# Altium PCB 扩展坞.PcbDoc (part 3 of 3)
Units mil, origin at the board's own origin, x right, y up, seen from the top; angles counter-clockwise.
Board outline 3543.31 x 1968.5 mil, 4 copper layers (Top Layer 1, Layer1, Layer2, Bottom Layer 1), stack 62.337 mil thick; 191 components, 182 nets, 737 pads, 256 vias.
Unrouted connection lines stored in the file: 242.
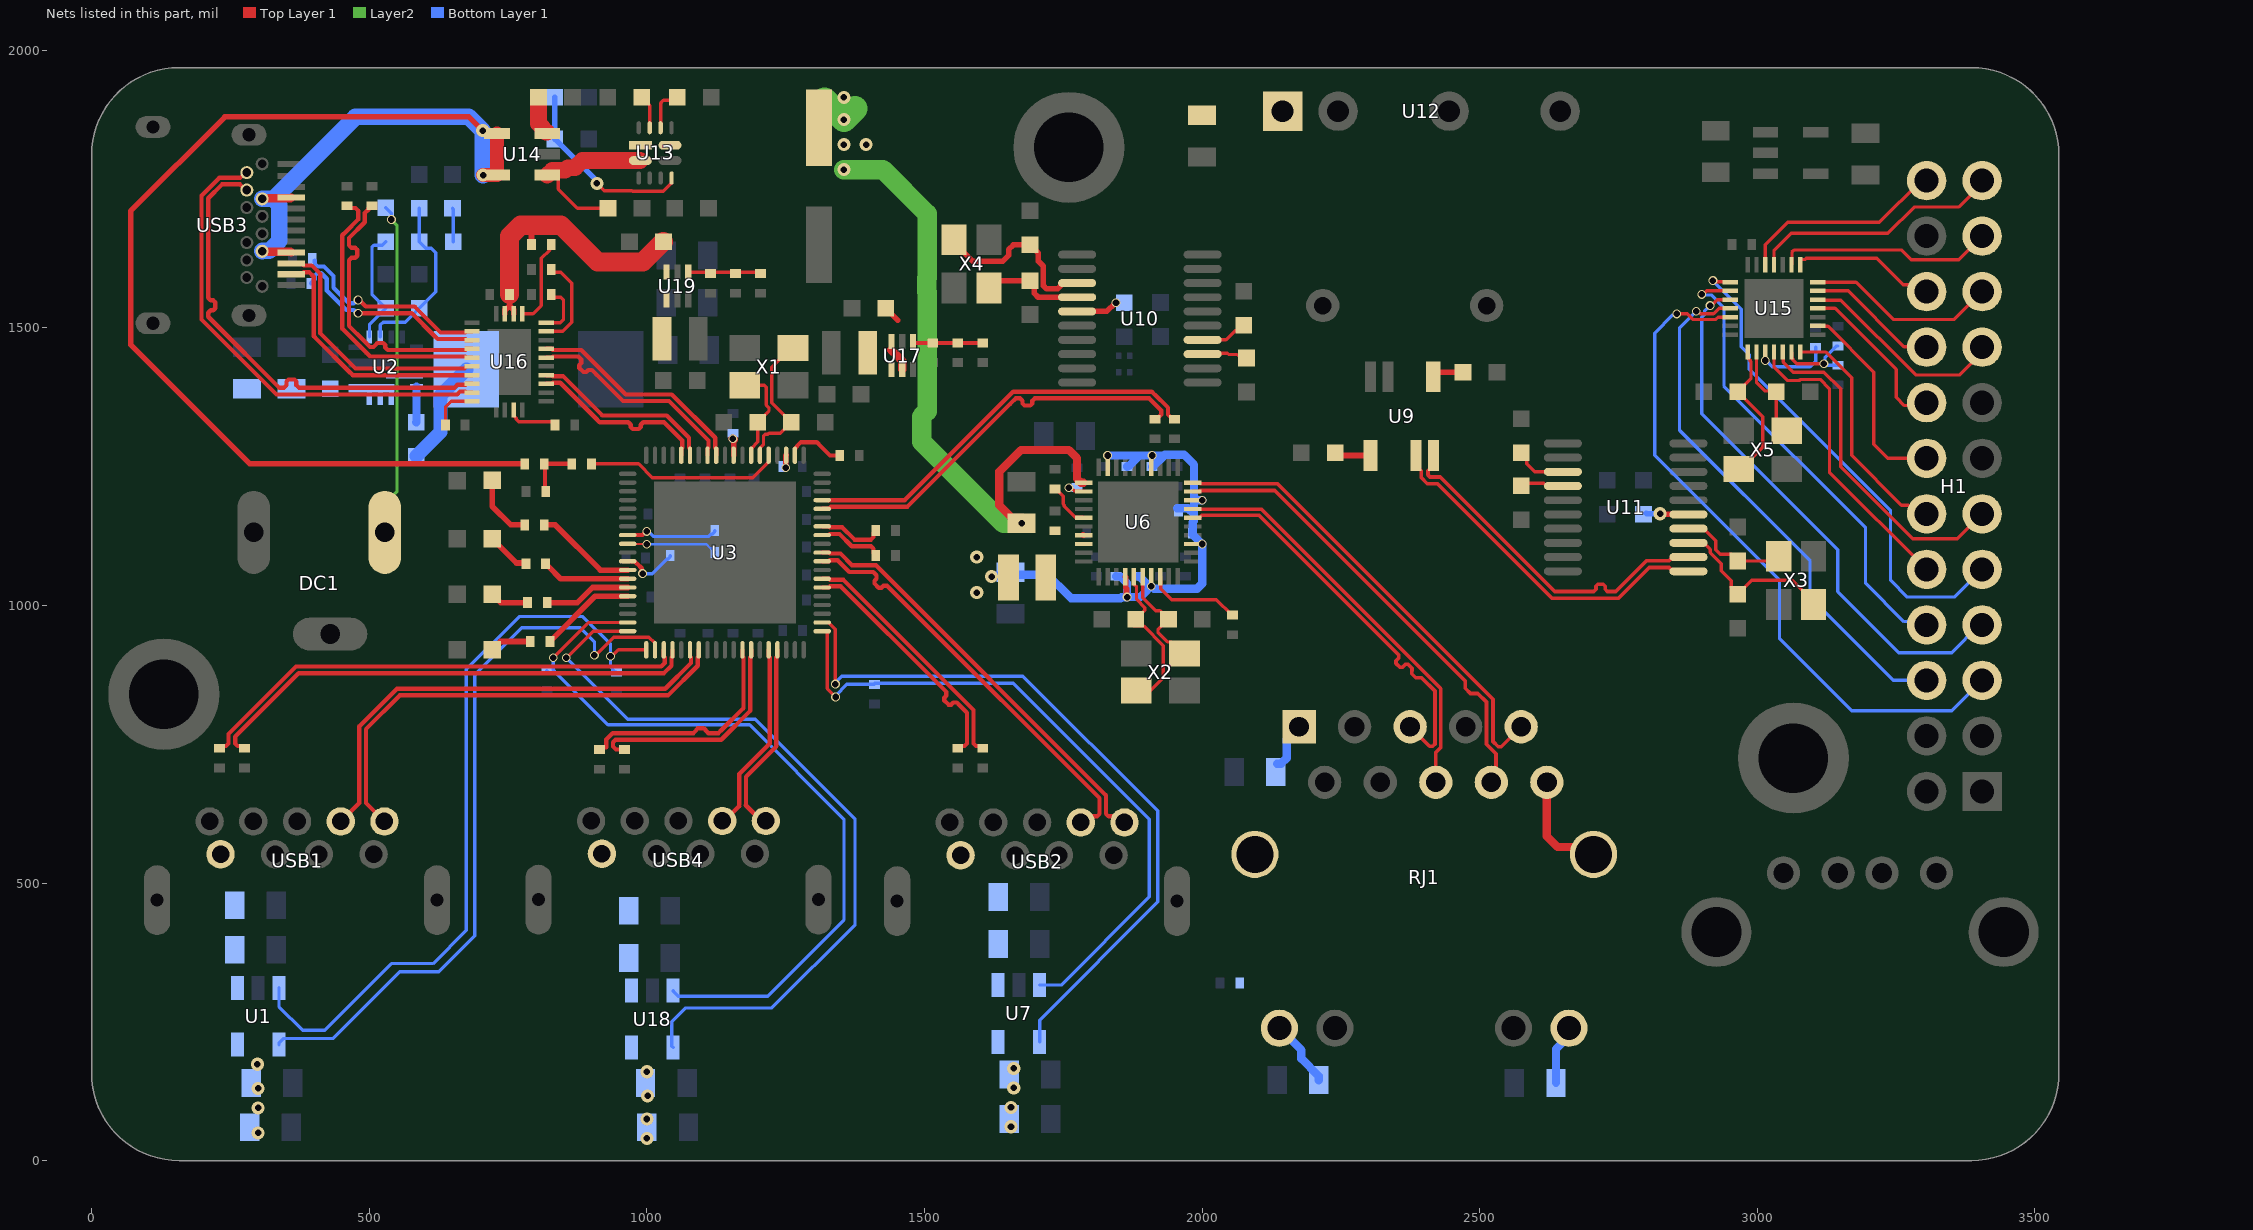
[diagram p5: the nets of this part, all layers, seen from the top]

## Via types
v1: diameter 15.75, hole 11.81, Top Layer 1 to Bottom Layer 1, tented both sides, 127 vias
v2: diameter 23.62, hole 11.81, Top Layer 1 to Bottom Layer 1, tented both sides, 118 vias
v3: diameter 15.75, hole 11.81, Top Layer 1 to Bottom Layer 1, 10 vias
v4: diameter 23.62, hole 11.81, Top Layer 1 to Bottom Layer 1, 1 vias

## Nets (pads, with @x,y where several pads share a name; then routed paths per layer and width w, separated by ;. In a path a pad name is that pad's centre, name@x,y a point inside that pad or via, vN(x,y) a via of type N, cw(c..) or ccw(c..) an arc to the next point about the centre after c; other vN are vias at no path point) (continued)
MDI2_N: RJ1.P6 U6.7 | length 753.1
  Top Layer 1 w6.7: U6.7@1983.4,1173.62 1983.99,1173.03 1996.97,1173.03 1997.03,1172.97 2107.16,1172.97 2110.95,1169.19 2430.02,850.11 2430.02,745.9 2430,744.04 2420.9,734.94 RJ1.P6@2420.9,681.45
MDI2_P: RJ1.P5 U6.6 | length 751.6
  Top Layer 1 w6.7: U6.6@1983.4,1157.87 1995.21,1157.87 1999.61,1162.27 2102.73,1162.27 2340,925 2354.18,910.82 2354.18,905.27 2349.23,900.33 2349.23,895.61 2356.32,888.52 2361.04,888.52 2366.4,893.88 2371.12,893.88 2378.21,886.79 2378.21,882.07 2377.79,881.65 2377.79,876.93 2384.88,869.85 2389.6,869.85 2395.15,869.85 2419.32,845.68 2419.32,834.32 2419.32,750.33 2415.4,746.41 2409.85,746.41 RJ1.P5@2374.8,781.45
MDI3_N: RJ1.P9 U6.10 | length 847.7
  Top Layer 1 w6.7: U6.10@1983.4,1220.87 1995.21,1220.87 1997.09,1218.99 2136.01,1218.99 2143.03,1211.97 2517.12,837.88 2524.15,830.85 2524.15,754.77 2533.36,745.56 2538.91,745.56 RJ1.P9@2574.8,781.45
MDI3_P: RJ1.P8 U6.9 | length 850
  Top Layer 1 w6.7: U6.9@1983.4,1205.12 1995.21,1205.12 1997.09,1206.99 2131.03,1206.99 2474.01,864.01 2474.01,850.99 2483.49,841.51 2496.51,841.51 2512.15,825.88 2512.15,749.8 2529.27,732.67 2529.27,689.83 RJ1.P8@2520.9,681.45
MISO: H1.20 U15.15 | length 275.5
  Top Layer 1 w6: U15.15@3077.24,1613.74 3077.24,1622.19 3078.18,1623.12 3086.3,1623.12 3088.18,1625 3215,1625 3262.59,1577.41 3292.59,1577.41 H1.20@3305,1565 ; H1.20@3310.64,1550.64 H1.20@3320,1560
MODE: R26.2 U10.13 | length 80.5
  Top Layer 1 w6: U10.13@2001.06,1452.63 2002.65,1454.22 2045.78,1454.22 2048,1452 2063,1452 R26.2@2075,1440
MOSI: H1.21 U15.16 | length 391.9
  Top Layer 1 w6: U15.16@3061.5,1613.74 3062.44,1614.68 3062.44,1636.49 3065.95,1640 3260,1640 3277.43,1622.57 3362.57,1622.57 H1.21@3405,1665
NetC17_1: C17.1 U2.7 | length 64.2
  Bottom Layer 1 w15: C17.1@585,1330 585.06,1330.06 585.06,1384.94 585.12,1385 U2.7@585.12,1394.18
NetC18_1: C18.1 R2.1 R3.2 U2.2 | length 314.5
  Bottom Layer 1 w6: U2.2@520.16,1483.55 520.16,1505.16 525,1510 565,1510 R3.2@590,1535 620,1565 620,1635 612,1643 602,1643 C18.1@590,1655 R2.1@590,1715
NetC18_2: C18.2 R1.2 | length 60.5
  Bottom Layer 1 w6: R1.2@650,1715 651.18,1713.82 C18.2@651.18,1655
NetC26_2: C26.2 U13.11 | length 60.8
  Top Layer 1 w6: C26.2@990.59,1915 1005.16,1900.43 U13.11@1005.16,1860.27
NetC43_1: C43.1 RJ1.P1 | length 87.3
  Bottom Layer 1 w15: C43.1@2135,715 2142.5,715 2152.5,725 2152.5,759.16 RJ1.P1@2174.8,781.45
NetC55_2: C55.2 U6.22 | length 29.1
  Top Layer 1 w6: v1(1760.21,1211.66) 1763.8,1211.66 1769.41,1206.06 1785.66,1206.06 U6.22@1786.6,1205.12
NetC60_1: C60.1 U9.6 | length 65.4
  Top Layer 1 w10: C60.1@2240,1275 2245,1270 U9.6@2303.31,1270
NetC61_2: C61.2 U9.3 | length 57.2
  Top Layer 1 w10: U9.3@2416.5,1411.73 2416.5,1412.2 2424.3,1420 C61.2@2470,1420
NetC62_1: C62.1 U11.5 | length 77
  Top Layer 1 w10: v2(2825,1165) 2825.59,1164.41 2875.47,1164.41 U11.5@2876.06,1163.82
  Bottom Layer 1 w10: C62.1@2800,1166.18 2801.18,1165 v2(2825,1165)
NetC63_2: C63.2 U10.5 | length 76.5
  Top Layer 1 w10: U10.5@1775,1529.4 1828.25,1529.4 1843.85,1545 v1(1845,1545)
NetC64_2: C64.2 U11.14 | length 81.2
  Top Layer 1 w6: C64.2@2575,1210 2585,1220 2615.62,1220 2620.62,1215 U11.14@2650,1215
NetC65_2: C65.2 U10.14 | length 89.5
  Top Layer 1 w6: U10.14@2001.06,1478.22 2043.22,1478.22 2059.51,1494.51 2070.7,1494.51 C65.2@2080,1503.82
NetC78_2: C78.2 R6.1 R7.2 U17.1 | length 126.8
  Top Layer 1 w7.74: U17.1@1479.69,1475.2 1479.69,1474.36 1481.33,1472.72 R6.1@1605,1472.72
NetC79_2: C79.2 R8.1 R9.2 U19.1 | length 131.3
  Top Layer 1 w6: U19.1@1074.69,1600.2 1202.52,1600.2 R8.1@1205,1597.72
NetC89_1: C89.1 R32.2 U15.6 | length 144
  Top Layer 1 w6: U15.6@3061.5,1456.26 3062.44,1455.32 3062.44,1445.48 3063.9,1444.02 3063.9,1441.98 3070.88,1435 v1(3120,1435)
  Bottom Layer 1 w6: C89.1@3145,1432.72 3122.28,1432.72 v1(3120,1435) 3121.87,1436.87 3121.87,1446.12 3143.03,1467.28 R32.2@3145,1467.29
NetLED1_2: LED1.2 R44.1 | length 119
  Top Layer 1 w10: LED1.2@721.47,1225.14 721.47,1178.53 755,1145 R44.1@780,1145
NetLED2_2: LED2.2 R45.1 | length 69.8
  Top Layer 1 w10: LED2.2@721.47,1020.14 736.61,1005 R45.1@785,1005
NetLED3_2: LED3.2 R46.1 | length 79.5
  Top Layer 1 w10: LED3.2@721.47,1120.14 765.27,1076.34 780.94,1076.34 R46.1@782.28,1075
NetLED4_2: LED4.2 R47.1 | length 74.7
  Top Layer 1 w10: LED4.2@721.47,920.14 736.34,935 R47.1@790,935
NetR4_1: R4.1 R5.2 U2.1 | length 213.2
  Bottom Layer 1 w6: U2.1@500.48,1483.55 500.48,1505.48 R5.2@530,1535 505,1560 505,1645 508.51,1648.51 523.51,1648.51 R4.1@530,1655
NetR10_1: R10.1 U16.23 | length 170.5
  Top Layer 1 w6: U16.23@819.06,1493.5 848.5,1493.5 865,1510 865,1580 845,1600 832.59,1600 827.72,1604.87 R10.1@827.72,1605
NetR11_1: R11.1 U16.24 | length 94.8
  Top Layer 1 w6: U16.24@819.06,1509.25 844.25,1509.25 850,1515 850,1550 845,1555 832.59,1555 827.72,1559.87 R11.1@827.72,1560
NetR12_1: R12.1 U16.25 | length 157.8
  Top Layer 1 w6: U16.25@775.75,1525 795,1525 810,1540 810,1625 825,1640 825,1647.28 R12.1@827.71,1650
NetR13_2: R13.2 U16.10 | length 84.4
  Top Layer 1 w6: R13.2@637.29,1325 637.29,1357.29 647.51,1367.51 U16.10@685.2,1367.51
NetR16_2: R16.2 U13.10 | length 78.9
  Top Layer 1 w6: U13.10@1024.84,1860.27 1024.84,1904.84 1030,1910 1050,1910 R16.2@1055,1915
NetR17_2: R17.2 U16.13 | length 93.2
  Top Layer 1 w6: U16.13@760.01,1351.76 760.01,1341.92 764.82,1337.1 764.82,1335.08 768.92,1330.98 829.7,1330.98 834.57,1326.11 R17.2@834.57,1325
NetR19_2: R19.2 U3.47 | length 30.2
  Top Layer 1 w10: U3.47@1156.4,1270.4 v1@1156.4,1298.4
  Top Layer 1 w15: v1(1155,1300) 1155,1299.8 v1@1156.4,1298.4
NetR20_1: R20.1 RJ1.11 | length 122.9
  Bottom Layer 1 w15: RJ1.11@2139.17,238.54 2178.74,198.97 2178.74,183.76 2210,152.5 R20.1@2210,145
NetR21_2: R21.2 U6.38 | length 171.5
  Top Layer 1 w6: U6.38@1924.37,1051.6 1925.31,1050.66 1925.31,1029.69 1945,1010 2025.75,1010 2053.03,982.71 R21.2@2055,982.71
NetR22_2: R22.2 U6.25 | length 82.3
  Top Layer 1 w6: R22.2@1735,1209.57 1736.97,1209.57 1750.05,1196.48 1750.05,1182.56 1751.84,1180.77 1751.84,1178.79 1771.83,1158.81 1785.66,1158.81 U6.25@1786.6,1157.87
NetR23_1: R23.1 U11.13 | length 95.1
  Top Layer 1 w6: R23.1@2575,1275 2585,1265 2585,1255 2599.41,1240.59 U11.13@2650,1240.59
NetR27_1: R27.1 U14.3 | length 70.4
  Top Layer 1 w30: R27.1@805,1915 805,1867.82 812.64,1860.18 812.64,1857.75 818,1852.4 U14.3@820.42,1852.4
NetR30_1: R30.1 RJ1.14 | length 108.2
  Bottom Layer 1 w15: R30.1@2637.4,140 2637.4,201.07 2660.83,224.49 RJ1.14@2660.83,238.54
NetR31_2: R31.2 U15.3 | length 126.2
  Bottom Layer 1 w6: v1@3012.55,1441.1 v1(3014.23,1441.1) 3015.9,1441.1 3027,1430 3095,1430 3105,1440 R31.2@3105,1465
NetR33_1: R33.1 RJ1.P10 RJ1.SHIELD0 RJ1.SHIELD1 | length 194.9
  Top Layer 1 w15: RJ1.P10@2620.9,681.45 2620.9,584.1 2640.05,564.95 2691.53,564.95 RJ1.SHIELD0@2704.92,551.55
NetR34_2: R34.2 U3.41 | length 22.7
  Top Layer 1 w10: v1(1250,1248.03) 1250.45,1248.48 1250.45,1269.95 U3.41@1250.9,1270.4
NetR37_2: R37.2 U3.68 | length 105.5
  Top Layer 1 w7.74: U3.68@965.5,1079.5 965.56,1079.44 U3.68@972.49,1079.44 ; v1(992.3,1057.24) 990.76,1058.77 990.76,1066.94 982.2,1075.51 981.34,1075.51 977.37,1079.47 U3.68@972.52,1079.47 ; U3.68@972.49,1079.44 U3.68@972.52,1079.47
  Bottom Layer 1 w6: v1(992.3,1057.24) 1009.53,1057.24 1035.44,1083.15 1037.41,1083.15 1042.29,1088.03 R37.2@1042.29,1090
NetR38_2: R38.2 U3.66 | length 164.5
  Top Layer 1 w4: U3.66@965.5,1110.9 965.95,1110.45 999.55,1110.45 v1(1000,1110)
  Bottom Layer 1 w4: v1(1000,1110) 1107.28,1110 1114.44,1102.84 1116.41,1102.84 1122.29,1096.97 R38.2@1122.29,1095
NetR39_2: R39.2 U3.65 | length 170
  Top Layer 1 w7.74: U3.65@965.5,1126.7 992.15,1126.73 998.71,1133.28 v1(999.79,1133.28) v1@1000.87,1133.28
  Bottom Layer 1 w6: v1(999.79,1133.28) 1002.43,1133.28 1011.55,1124.16 1111.45,1124.16 1115.44,1128.15 1117.41,1128.15 1122.29,1133.03 R39.2@1122.29,1135
NetR40_2: R40.2 U3.40 | length 107.8
  Top Layer 1 w7.74: U3.40@1266.7,1270.4 1266.7,1282.25 1270.59,1286.14 1270.59,1287.1 1277.51,1294.02 1305.98,1294.02 1309.99,1290.01 1330,1270 R40.2@1347.29,1270
NetR41_2: R41.2 R42.1 R43.1 | length 100.5
  Top Layer 1 w7.74: R43.1@817.72,1205 816.57,1206.14 816.57,1253.85 R41.2@815.43,1255 R42.1@865,1255
NetU4_1: U4.1 U17.4
NetU5_1: U5.1 U19.4
OC1: R18.2 U1.3 U3.1 | length 1378
  Top Layer 1 w6: v1(934.58,908.34) 937.22,908.34 948.88,920 U3.1@999,920
  Bottom Layer 1 w6: U1.3@337.4,311.18 337.4,277.6 380,235 420,235 540,355 615,355 675,415 675,885 770,980 885,980 934.58,930.42 v1(934.58,908.34) 934.58,890.42 938.16,886.84 938.16,884.87 943.03,880 R18.2@945,880
OC2: R36.2 U3.75 U18.3 | length 1387.5
  Top Layer 1 w6: v1(831.33,905.74) 850.46,924.87 894.79,969.2 U3.75@965.5,969.2
  Bottom Layer 1 w6: R36.2@820,882.71 824.87,877.84 837.16,877.84 ; v1(831.33,905.74) 831.33,883.67 837.16,877.84 ; U18.3@1047.4,306.18 1047.4,305 1056.21,296.18 1217.8,296.18 1355,433.38 1355,615 1185,785 930,785 837.16,877.84
OC3: R35.2 U3.20 U7.3 | length 1214
  Top Layer 1 w6: U3.20@1315.9,953.5 1323.85,953.5 1324.71,952.63 1324.71,850.29 v1(1340,835)
  Bottom Layer 1 w6: v1(1340,835) 1340,837.64 1360.08,857.71 R35.2@1410,857.71 ; R35.2@1410,860 1660,860 1905,615 1905,475 1746.18,316.18 U7.3@1707.4,316.18
P1C_SS_RX_N: U16.8 USB3.B10 | length 865.1
  Top Layer 1 w7.74: USB3.B10@279.59,1747.98 277.38,1747.98 267.11,1758.26 234.86,1758.26 210,1733.4 210,1565 210,1553.88 214.53,1549.35 219.14,1549.35 222.68,1545.8 222.68,1535.16 219.14,1531.61 214.53,1531.61 210,1527.08 210,1520 220,1510 335,1395 338,1392 346.58,1392 351.12,1396.53 351.12,1403.45 354.66,1407 365.31,1407 368.86,1403.45 368.86,1396.53 373.39,1392 395,1392 653.45,1392 658.58,1397.14 673.48,1397.14 675.36,1399.01 U16.8@685.2,1399.01
P1C_SS_RX_P: U16.9 USB3.B11 | length 867.8
  Top Layer 1 w7.74: USB3.B11@279.58,1779.48 276.6,1779.48 267.11,1770 230,1770 198.26,1738.26 198,1738 198,1515.03 333.03,1380 658.42,1380 663.55,1385.14 673.48,1385.14 675.36,1383.26 U16.9@685.2,1383.26
P1C_SS_TX_N: C31.2 U16.5 | length 503.2
  Top Layer 1 w7.74: C31.2@460,1719.57 464,1715.57 475.47,1715.57 480,1711.03 480,1695 458.54,1673.54 451.51,1666.51 451.51,1600 451.51,1498.49 458.54,1491.46 494.85,1455.15 501.88,1448.12 673.48,1448.12 675.36,1446.25 U16.5@685.2,1446.25
P1C_SS_TX_P: C30.2 U16.4 | length 503.5
  Top Layer 1 w7.74: C30.2@505,1719.57 503.03,1719.57 499.02,1715.57 499.02,1713.6 492,1706.57 492,1690.03 463.51,1661.54 463.51,1655 463.51,1648.42 468.05,1643.88 474.97,1643.88 478.51,1640.34 478.51,1629.69 474.97,1626.14 468.05,1626.14 463.51,1621.61 463.51,1600 463.51,1503.46 490,1476.97 501.41,1465.57 507.82,1465.57 514.66,1472.41 525.31,1472.41 528.86,1468.86 528.86,1464.66 533.39,1460.12 555,1460.12 673.48,1460.12 675.36,1462 U16.4@685.2,1462
PE1: U1.4 U3.2 | length 1329.6
  Top Layer 1 w6: v1(905.61,910.43) 908.24,910.43 940.56,942.75 948.97,942.75 949.16,942.56 981.84,942.56 982.03,942.75 1003.76,942.75 1014.09,932.42 1014.09,920.61 U3.2@1014.7,920
  Bottom Layer 1 w6: U1.4@337.4,208.82 337.4,211.19 346.21,220 435,220 555,340 625,340 690,405 690,875 775,960 880,960 905.61,934.39 v1(905.61,910.43)
PE2: U3.76 U18.4 | length 1410.4
  Top Layer 1 w6: v1(855,905.74) 855.74,905.74 903.5,953.5 U3.76@965.5,953.5
  Bottom Layer 1 w6: v1(855,905.74) 965.74,795 1195,795 1375,615 1375,425 1225,275 1070,275 1045,250 1045,206.22 U18.4@1047.4,203.82
PE3: U3.21 U7.4 | length 1320.3
  Top Layer 1 w6: U3.21@1315.9,969.2 1327.71,969.2 1339.59,957.33 v1(1339.59,858.26)
  Bottom Layer 1 w6: v1(1339.59,858.26) 1339.59,860.9 1351.28,872.59 1677.41,872.59 1920,630 1920,465.86 1707.4,253.26 U7.4@1707.4,213.82
PR1: R48.1 R49.2 U13.6 | length 341.2
  Top Layer 1 w6: v2(910,1760) 923,1747 973.32,1747 974.13,1746.19 1029.38,1746.19 1044.53,1761.34 U13.6@1044.53,1769.73
  Bottom Layer 1 w10: R49.2@834.41,1915 R48.1@834.41,1840 907.39,1767.02 907.39,1762.61 v2(910,1760)
RTS0: H1.23 U15.18 | length 455.4
  Top Layer 1 w6: U15.18@3030,1613.74 3030,1638.95 3061.05,1670 3235,1670 3282.5,1717.5 3362.5,1717.5 3405,1760 H1.23@3405,1765
RX0_N: U3.53 U16.17 | length 331
  Top Layer 1 w7.74: U16.17@819.06,1399.01 828.9,1399.01 830.78,1400.89 844.12,1400.89 907.97,1337.03 915,1330 945,1330 966.61,1330 971.14,1325.47 971.14,1321.3 974.69,1317.76 985.34,1317.76 988.88,1321.3 988.88,1325.47 993.42,1330 1010,1330 1030.91,1330 1063.85,1297.06 1063.85,1284.1 1062,1282.25 U3.53@1062,1270.4
RX0_P: U3.52 U16.18 | length 335.9
  Top Layer 1 w7.74: U16.18@819.06,1414.76 828.9,1414.76 830.78,1412.89 849.09,1412.89 919.97,1342 1035.88,1342 1075.85,1302.03 1075.85,1284.1 1077.7,1282.25 U3.52@1077.7,1270.4
RX1_N: U3.6 USB1.6 | length 854.3
  Top Layer 1 w7.74: USB1.6@448.74,610.87 482.11,644.23 482.11,782.08 550.03,850 1033.22,850 1079.6,896.38 1079.6,906.25 1077.7,908.15 U3.6@1077.7,920
RX1_P: U3.7 USB1.5 | length 854.3
  Top Layer 1 w7.74: USB1.5@527.48,610.87 494.11,644.24 494.11,777.11 555,838 1038.19,838 1091.6,891.41 1091.6,906.25 1093.5,908.15 U3.7@1093.5,920
RX2_N: U3.15 USB4.6 | length 347.6
  Top Layer 1 w7.74: USB4.6@1133.75,605.87 1166.26,638.39 ; 1166.52,641.9 1166.52,696.52 1221.3,751.3 1221.3,906.25 1219.4,908.15 U3.15@1219.4,920
RX2_P: U3.16 USB4.5 | length 351.9
  Top Layer 1 w7.74: USB4.5@1212.47,605.87 1178.26,640.09 1178.52,640.34 1178.52,691.55 1233.3,746.33 1233.3,906.25 1235.2,908.15 U3.16@1235.2,920
RX3_N: U3.28 USB2.6 | length 761.4
  Top Layer 1 w7.74: U3.28@1315.9,1079.5 1327.75,1079.5 1329.6,1081.35 1343.65,1081.35 1364.71,1060.29 1395.29,1060.29 1407.74,1060.29 1413.59,1054.44 1413.59,1048.03 1409.98,1044.42 1409.98,1039.4 1417.51,1031.87 1422.52,1031.87 1426.13,1035.48 1432.55,1035.48 1464.01,1004.01 1815.14,652.89 1815.14,624.55 1810.61,620.02 1790.06,620.02 USB2.6@1781.77,611.73
RX3_P: U3.29 USB2.5 | length 764.4
  Top Layer 1 w7.74: U3.29@1315.9,1095.2 1327.75,1095.2 1329.6,1093.35 1348.62,1093.35 1369.68,1072.29 1412.71,1072.29 1827.14,657.86 1827.14,624.55 1831.68,620.02 1852.23,620.02 USB2.5@1860.51,611.73
RX4_N: C39.1 U3.35 | length 742.5
  Top Layer 1 w7.74: U3.35@1315.9,1189.7 1327.75,1189.7 1327.81,1189.63 1464.63,1189.63 1659.74,1384.74 1909.54,1384.74 1914.28,1380 1914.65,1380 1938.5,1356.14 1938.5,1343.97 1943.04,1339.43 1946,1339.43 C39.1@1950,1335.43
RX4_P: C40.1 U3.34 | length 740.8
  Top Layer 1 w7.74: U3.34@1315.9,1173.9 1327.75,1173.9 1331.74,1177.89 1469.5,1177.89 1655,1363.4 1664.6,1373 1672.08,1373 1676.61,1368.47 1676.61,1363.58 1680.16,1360.03 1690.8,1360.03 1694.35,1363.58 1694.35,1368.47 1698.88,1373 1720,1373 1890,1373 1904.68,1373 1926.5,1351.17 1926.5,1343.97 1921.97,1339.43 1919.01,1339.43 C40.1@1915,1335.43
RXD0: H1.9 U15.22 | length 903.1
  Top Layer 1 w6: v1(2920,1585) 2921.82,1583.18 2950.32,1583.18 U15.22@2951.26,1582.24
  Bottom Layer 1 w6: v1(2920,1585) 2971.19,1533.81 2971.19,1465.41 2985.39,1451.22 2985.39,1425.39 3240,1170.78 3240,1045 3270,1015 3355,1015 H1.9@3405,1065
RXD1: H1.11 U15.5 | length 609.1
  Top Layer 1 w6: U15.5@3045.75,1456.26 3046.69,1455.32 3046.69,1438.31 3065,1420 3120,1420 3150,1390 3150,1250 3280,1120 3360,1120 H1.11@3405,1165
S_XI: R24.1 U11.4 X3.3 | length 199.6
  Top Layer 1 w6: U11.4@2876.06,1138.22 2903.19,1138.22 2925,1116.41 2925,1100 2933,1092 2953,1092 R24.1@2965,1080 3030.2,1080 X3.3@3038.51,1088.3
S_XO: C66.1 U11.3 X3.1 | length 313
  Top Layer 1 w6: U11.3@2876.06,1112.63 2903.19,1112.63 2915,1100.82 2915,1095.26 2935,1075.26 2935,1062.5 2953,1044.5 2953,1032 C66.1@2965,1020 2990,1045 3063.11,1045 3101.49,1006.62 X3.1@3101.49,1001.7
SCK: H1.19 U15.14 | length 344.8
  Top Layer 1 w6: U15.14@3108.74,1582.24 3177.76,1582.24 3245,1515 3355,1515 H1.19@3405,1565
SCL: H1.16 U15.11 | length 300.1
  Top Layer 1 w6: U15.11@3108.71,1535 3140,1535 3250,1425 3250,1375 3265,1360 3300,1360 H1.16@3305,1365
SCS0: H1.18 U15.13 | length 256.4
  Top Layer 1 w6: U15.13@3108.74,1566.5 3163.5,1566.5 3264.08,1465.92 3304.08,1465.92 H1.18@3305,1465 ; H1.18@3305,1467.46 3312.54,1467.46 H1.18@3320,1460
SCS1: H1.12 U15.7 | length 430.4
  Top Layer 1 w6: U15.7@3077.24,1456.26 3123.74,1456.26 3170,1410 3170,1270 3259.58,1180.42 3272.03,1180.42 3277.45,1175 3295,1175 H1.12@3305,1165
SDA: H1.17 U15.12 | length 379.1
  Top Layer 1 w6: U15.12@3108.74,1550.74 3109.68,1549.8 3150.2,1549.8 3285,1415 3365,1415 3405,1455 H1.17@3405,1465
SS1_RX_N: U16.7 USB3.A11 | length 467
  Top Layer 1 w7.74: USB3.A11@359.32,1596.41 378.51,1596.41 382.35,1600.26 391.79,1600.26 400,1592.05 400,1485 407.03,1477.97 463.22,1421.78 470.25,1414.75 U16.7@685.2,1414.75
SS1_RX_P: U16.6 USB3.A10 | length 468.6
  Top Layer 1 w7.74: USB3.A10@359.32,1616.11 378.51,1616.11 382.35,1612.26 396.76,1612.26 412,1597.02 412,1489.97 475.22,1426.75 671.61,1426.75 675.36,1430.5 U16.6@685.2,1430.5
SS1_TX_N: C73.1 U16.3 | length 358.9
  Top Layer 1 w7.74: v1(480,1526.25) 493.91,1526.25 576.78,1526.25 616.38,1486.65 623.41,1479.62 673.49,1479.62 675.36,1477.75 U16.3@685.2,1477.75
  Bottom Layer 1 w7.74: C73.1@395,1580 C73.1@399,1584 ; 402.52,1587.52 402.52,1593.89 407.05,1598.42 413.46,1598.42 423.59,1588.3 423.59,1567.18 458.64,1532.13 471.96,1532.13 477.83,1526.25 v1(480,1526.25)
SS1_TX_P: C72.1 U16.2 | length 358.2
  Top Layer 1 w7.74: v1(480,1550) 482.17,1550 493.91,1538.25 581.75,1538.25 628.38,1491.62 673.49,1491.62 675.36,1493.49 U16.2@685.2,1493.49
  Bottom Layer 1 w7.74: C72.1@401.72,1621 401.72,1615.75 407.05,1610.42 418.44,1610.42 435.59,1593.27 435.59,1572.15 463.61,1544.13 471.96,1544.13 477.83,1550 v1(480,1550)
SW: C17.2 L2.1 U2.6 | length 193.5
  Bottom Layer 1 w25: C17.2@585,1268.82 628.45,1312.26 628.45,1378.44 L2.1@675,1425
SW2: L3.1 U6.28
SWDIO/TMS: H1.5 U15.26 | length 1241.5
  Top Layer 1 w6: v1(2855,1525) 2873.97,1525 2883.97,1515 2925.18,1515 2929.44,1519.26 U15.26@2951.26,1519.26
  Bottom Layer 1 w6: v1(2855,1525) 2853.13,1523.13 2848.13,1523.13 2815,1490 2815,1270 3040,1045 3040,940 3170,810 3350,810 H1.5@3405,865
SYS+5V: C37.1 C44.2 C45.2 C57.2 C76.2 C77.2 C82.2 C83.2 C93.2 C94.2 C97.2 C98.2 C101.2 R12.2 U1.5 U6.21 U6.27 U7.5 U12.1 U13.1 U13.8 U16.26 U16.27 U17.3 U17.5 U18.5 U19.3 | length 1861.4
  Top Layer 1 w10: U16.27@744.25,1525 744.25,1532.72 745.31,1533.78 746.86,1533.78 752.71,1539.64 ; C77.2@752.71,1560 752.71,1539.64 ; U16.26@760,1525 760,1532.72 758.94,1533.78 758.57,1533.78 752.71,1539.64 ; R12.2@792.28,1650 792.28,1682.28 795,1685 ; C57.2@1430.59,1535 1452.24,1513.35 ; U6.27@1785.54,1127.44 U6.27@1786.6,1126.38
  Top Layer 1 w15: 1440,1460 1450.31,1449.69 1450.59,1449.69 1460.01,1440.27 U17.5@1460.01,1424.8 ; v2(1675,1147.6) 1667.5,1147.6 1635,1180.1 1635,1241.17 1673.83,1280 1760,1280 1774.79,1265.21 1774.79,1228 1781.91,1220.87 U6.21@1786.6,1220.87
  Top Layer 1 w35: C77.2@752.71,1560 752.71,1664.5 773.22,1685 795,1685 845,1685 911.5,1618.5 992.72,1618.5 1029.22,1655 C76.2@1030,1655
  Layer2 w35: v2(1355,1785) 1425,1785 1505,1705 1505,1589.64 1504.41,1589.05 1504.41,1564.71 1505,1564.12 1505,1350 1495,1340 1495,1295 1642.4,1147.6 v2(1675,1147.6)
  Layer2 w45: 1320,1910 v2(1355,1875) 1375,1895 ; U12.1@2140,1895 U12.1@2150,1885
  other v2: 1000,40 300,50 1655.84,61.03 1000,75 300,95 1655.84,96.03 1001.48,116.48 300,130 1660.84,131.03 1000,160 1660.84,166.03 298.52,173.52 1355,1830 1395,1830 1355,1915
TCK: H1.8 U15.23 | length 846.6
  Top Layer 1 w6: v1(2900,1560) 2902.64,1560 2909.14,1566.5 U15.23@2951.26,1566.5
  Bottom Layer 1 w6: v1(2900,1560) 2900.84,1559.16 2916.87,1559.16 2940,1536.03 2940,1395 3195,1140 3195,1040 3264.08,970.92 3299.08,970.92 H1.8@3305,965
TDI: H1.6 U15.25 | length 964.3
  Top Layer 1 w6: v1(2890,1530) 2892.64,1530 2897.51,1525.13 2921.16,1525.13 2931.03,1535 U15.25@2951.27,1535
  Bottom Layer 1 w6: v1(2890,1530) 2860,1500 2860,1315 3095,1080 3095,1015 3245,865 H1.6@3305,865
TDO: H1.7 U15.24 | length 989.7
  Top Layer 1 w6: v1(2915,1540) 2917.38,1540 2928.12,1550.74 U15.24@2951.26,1550.74
  Bottom Layer 1 w6: v1(2915,1540) 2904.87,1529.87 2904.87,1523.84 2900,1518.97 2900,1345 3145,1100 3145,1025 3255,915 3350,915 3400,965 H1.7@3405,965
TRST: H1.14 U15.9 | length 371.2
  Top Layer 1 w6: U15.9@3108.74,1503.5 3109.68,1502.56 3127.44,1502.56 3210,1420 3210,1290 3235,1265 H1.14@3305,1265
TX0_N: U3.50 U16.20 | length 400.1
  Top Layer 1 w7.74: U16.20@819.06,1446.26 828.9,1446.26 830.78,1448.14 863.14,1448.14 876.86,1448.14 877.54,1447.46 882.07,1442.92 882.07,1436.51 878.3,1432.73 878.3,1427.72 885.82,1420.19 890.84,1420.19 894.62,1423.97 901.03,1423.97 910,1415 957,1368 1040.03,1368 1111.1,1296.93 1111.1,1284.15 1109.2,1282.25 U3.50@1109.2,1270.4
TX0_P: U3.49 U16.21 | length 402.6
  Top Layer 1 w7.74: U16.21@819.06,1462.01 828.9,1462.01 830.78,1460.14 881.84,1460.14 961.97,1380 1045,1380 1123.1,1301.9 1123.1,1284.15 1125,1282.25 U3.49@1125,1270.4
TX1_N: C33.2 U3.3 | length 900.5
  Top Layer 1 w7.74: C33.2@230,742.71 234.01,746.72 241.97,746.72 246.5,751.25 246.5,768.47 368.03,890 1025.97,890 1032.35,896.38 1032.35,906.3 1030.5,908.15 U3.3@1030.5,920
TX1_P: C32.2 U3.4 | length 900.5
  Top Layer 1 w7.74: C32.2@275,742.71 271,746.72 263.04,746.72 258.5,751.25 258.5,763.5 373,878 544.97,878 1030.94,878 1044.35,891.41 1044.35,906.3 1046.2,908.15 U3.4@1046.2,920
TX2_N: C28.2 U3.12 | length 412.3
  Top Layer 1 w7.74: C28.2@915,740.43 919.01,744.43 926.97,744.43 926.97,758.44 938.53,770 1080,770 1083.87,770 1088.4,774.53 1088.4,775.39 1091.95,778.93 1102.6,778.93 1106.14,775.39 1106.14,774.53 1110.68,770 1129.05,770 1135,775.95 1174.05,815 1174.05,906.3 1172.2,908.15 U3.12@1172.2,920
TX2_P: C27.2 U3.13 | length 412
  Top Layer 1 w7.74: C27.2@960,740.43 944.57,740.43 938.97,746.03 938.97,753.47 943.5,758 1134.02,758 1186.05,810.03 1186.05,906.3 1187.9,908.15 U3.13@1187.9,920
TX3_N: C35.2 U3.25 | length 448.6
  Top Layer 1 w7.74: U3.25@1315.9,1032.2 1327.75,1032.2 1329.78,1034.23 1349.17,1034.23 1524.2,859.2 1539.48,843.92 1539.48,837.51 1535.78,833.81 1535.78,828.79 1543.31,821.27 1548.33,821.27 1552.02,824.96 1558.44,824.96 1561.7,821.7 1576.63,806.76 1576.63,751.25 1572.1,746.72 1564.01,746.72 C35.2@1560,742.71
TX3_P: C34.2 U3.26 | length 450.9
  Top Layer 1 w7.74: U3.26@1315.9,1048 1327.75,1048 1329.78,1045.97 1354.03,1045.97 1588.37,811.63 1588.37,751.25 1592.91,746.72 1601,746.72 C34.2@1605,742.71
TX4_N: C36.1 U3.32 | length 117.8
  Top Layer 1 w7.74: U3.32@1315.9,1142.4 1327.75,1142.4 1329.6,1140.55 1352.04,1140.55 1374.09,1118.5 1403.75,1118.5 1408.28,1123.03 1408.28,1131 C36.1@1412.28,1135
TX4_P: C29.1 U3.31 | length 117.8
  Top Layer 1 w7.74: U3.31@1315.9,1126.7 1327.75,1126.7 1329.6,1128.55 1347.07,1128.55 1369.12,1106.5 1403.75,1106.5 1408.28,1101.97 1408.28,1094 C29.1@1412.28,1090
TXD0: H1.24 U15.19 | length 374.2
  Top Layer 1 w6: U15.19@3014.26,1613.74 3014.26,1649.26 3055,1690 3220,1690 3295,1765 H1.24@3305,1765
TXD1: H1.10 U15.4 | length 542.3
  Top Layer 1 w6: U15.4@3029.96,1456.26 3029.96,1430.04 3055,1405 3075.69,1405 3077.69,1407 3113.49,1407 3130,1390.49 3130,1240 H1.10@3305,1065
USBLED1: R44.2 U3.69 | length 183.7
  Top Layer 1 w10: R44.2@815.43,1145 835,1145 916.3,1063.7 U3.69@965.5,1063.7
USBLED2: R46.2 U3.70 | length 160.1
  Top Layer 1 w10: R46.2@817.71,1075 817.71,1073.03 820.59,1070.15 822.56,1070.15 844.71,1048 U3.70@965.5,1048
USBLED3: R45.2 U3.71 | length 158.6
  Top Layer 1 w10: R45.2@818.15,1005 R45.2@820.43,1005 875,1005 902.2,1032.2 U3.71@965.5,1032.2
USBLED4: R47.2 U3.72 | length 175
  Top Layer 1 w10: R47.2@825.43,935 825.43,936.97 828.3,939.84 830.27,939.84 906.93,1016.5 U3.72@965.5,1016.5
VBUS: R41.1 U14.4 U14.5 USB3.A4 USB3.A9 USB3.B4 USB3.B9 | length 2624.8
  Top Layer 1 w10: v2(704.4,1855) 679.4,1880 240,1880 70.19,1710.19 70.19,1469.81 285,1255 R41.1@780,1255
  Top Layer 1 w15: USB3.B4@307.14,1637.76 308.13,1636.77 358.33,1636.77 USB3.A9@359.32,1635.78 ; USB3.B9@307.15,1732.24 308.14,1733.23 358.33,1733.23 USB3.A4@359.32,1734.22
  Top Layer 1 w25: v2(705,1775) U14.5@730,1775 ; U14.5@730,1777.85 U14.4@730,1849.8
  Bottom Layer 1 w30: USB3.B4@307.14,1637.76 307.82,1638.43 319.91,1638.43 337.96,1656.48 337.96,1721.52 327.24,1732.24 ; USB3.B9@307.15,1732.24 327.24,1732.24 ; v2(705,1775) 704.4,1775.6 v2(704.4,1855) 679.4,1880 475,1880 327.24,1732.24
VBUS2: C84.2 C85.2 U1.1 USB1.1
VBUS3: C95.2 C96.2 U7.1 USB2.1
VBUS4: C99.2 C100.2 U18.1 USB4.1
VBUS_C: R14.2 U13.2 U14.1 | length 313.2
  Top Layer 1 w6: U14.1@833.55,1777.6 840.2,1770.95 840.2,1749.8 875,1715 R14.2@930,1715
  Top Layer 1 w30: U14.1@820.9,1775 829.65,1783.75 852.99,1783.75 857.74,1788.5 870.98,1788.5 883.7,1801.23 U13.2@988.43,1801.23
VBUSET0: R42.2 U3.43 | length 352.9
  Top Layer 1 w6: R42.2@900.43,1255 985,1255 1009.85,1230.15 1190.96,1230.15 1219.4,1258.59 U3.43@1219.4,1270.4
VDD1V0: C50.2 C51.2 C52.2 C53.2 C54.2 C68.2 C69.2 C70.2 L3.2 U6.3 U6.8 U6.14 U6.19 U6.34 U6.37 | length 1007.8
  Top Layer 1 w10: U6.34@1861.38,1051.6 1862.44,1050.54 1862.44,1031.37 1863.9,1029.91 1863.9,1016.1 v1(1865,1015)
  Bottom Layer 1 w15: v4(1620.81,1051.86) 1622.46,1053.5 1653.5,1053.5 1655,1055 C54.2@1715,1055 ; C54.2@1717.34,1059.63 1763.8,1013.16 1853.24,1013.16 1854.94,1014.86 1864.86,1014.86 v1(1865,1015) ; v1(1829.89,1270) 1886.97,1270 ; C69.2@1845,1052.29 1845.38,1051.91 1853.24,1051.91 1864.86,1040.3 1864.86,1015.14 v1(1865,1015) ; C51.2@1865,1250 1865.37,1250.37 1867.34,1250.37 1886.97,1270 ; C70.2@1885,1052.29 1886.97,1052.29 1904.62,1034.63 1908.49,1034.63 v1(1908.64,1034.49) ; 1901.78,1027.84 1889.09,1015.14 1865.14,1015.14 v1(1865,1015) ; C52.2@1910,1250 1911.97,1250 1931.34,1269.37 ; v1@1913.33,1030 1991.21,1030 2000.35,1039.14 v1(2000.35,1110.63) ; C68.2@1955,1175 1975,1175 1985.43,1164.57 ; C50.2@1982.71,1128.03 v1@1999.97,1110.77 ; C50.2@1983.09,1127.66 1983.09,1149.8 1985.43,1152.14 1985.43,1164.57 ; 1985.43,1189.37 1985.43,1164.57 ; v1(2000.35,1189.37) 2000.21,1189.51 1990.92,1189.51 1985.43,1195 1985.43,1253.55 1967.36,1271.62 1932.96,1271.62 1931.34,1270 v1(1910,1270) 1886.97,1270
  other v2: 1594.19,1023.14 1594.19,1086.86
VIN: C19.1 C20.1 C21.1 DC1.1 R4.2 U2.8 | length 602
  Layer2 w6: DC1.1@528.15,1131.55 528.15,1182.61 550,1204.46 550,1685 v1(540,1695)
  Bottom Layer 1 w6: R4.2@530,1716.18 540,1706.18 v1(540,1695)
X_N: U9.5 U11.1 | length 640.9
  Top Layer 1 w6.7: U9.5@2385,1270 2385,1252.28 2394.75,1242.53 2394.75,1230.12 2405.7,1219.17 2423.86,1219.17 2630.03,1013 2749.97,1013 2805.22,1068.24 2841.19,1068.24 2847.99,1061.45 U11.1@2876.06,1061.45
X_P: U9.4 U11.2 | length 638.4
  Top Layer 1 w6.7: U9.4@2416.5,1270 2416.5,1252.28 2406.75,1242.53 2406.75,1235.09 2410.67,1231.17 2428.83,1231.17 2635,1025 2690,1025 2705.4,1025 2709.32,1028.92 2709.32,1034.61 2712.66,1037.95 2722.68,1037.95 2726.02,1034.61 2726.02,1028.92 2729.95,1025 2745,1025 2750,1030 2800.25,1080.24 2841.19,1080.24 2847.99,1087.04 U11.2@2876.06,1087.04
XI: C23.2 U3.45 X1.3 | length 177.8
  Top Layer 1 w6: X1.3@1176.7,1396.6 1211.49,1396.6 1215,1393.09 1215,1360.86 1220,1355.86 1220,1350 C23.2@1200,1330 1200,1294.31 1187.9,1282.21 U3.45@1187.9,1270.4
XI0: R25.1 U10.4 X4.3 | length 185.2
  Top Layer 1 w10: X4.3@1616.49,1571.7 1629.8,1585 R25.1@1690,1585 1698.11,1576.89 1698.11,1561.89 1705,1555 U10.4@1775,1555
XI2: C88.1 U15.1 X5.3 | length 261.9
  Top Layer 1 w6: X5.3@2966.69,1245.55 2970.63,1245.55 3010,1284.92 3010,1340 C88.1@2965,1385 2988.5,1408.5 2988.5,1438.64 2987.56,1439.58 2987.56,1441.97 2984.05,1445.48 2983.7,1445.48 2982.76,1446.42 U15.1@2982.76,1456.26
XO: C22.1 U3.44 X1.1 | length 263.4
  Top Layer 1 w6: U3.44@1203.7,1270.4 1203.7,1282.72 1210,1289.02 1210,1304.49 1213.51,1308 1217.9,1308 1219.9,1310 1240,1310 C22.1@1260,1330 1225,1365 1225,1429.15 1259.35,1463.5 X1.1@1263.3,1463.5
XO0: C67.1 U10.3 X4.1 | length 325.7
  Top Layer 1 w10: X4.1@1553.51,1658.31 1553.51,1653.38 1586.89,1620 1641.11,1620 1651.43,1630.32 1651.43,1640.84 1660,1649.41 C67.1@1690,1649.41 1705,1634.41 1705,1620 1714,1611 1714,1575.86 1719.86,1570 1739.85,1570 1745.71,1575.86 1745.71,1577.25 1749.05,1580.59 U10.3@1775,1580.59
XO2: C87.2 U15.2 X5.1 | length 175.9
  Top Layer 1 w6: U15.2@2998.5,1456.26 2998.5,1401.5 3013.92,1386.08 3033.33,1386.08 C87.2@3034.41,1385 3034.41,1333.35 X5.1@3053.31,1314.45
XTAL1: C42.1 U6.35 X2.1 | length 315.8
  Top Layer 1 w6: X2.1@1871.69,846.53 1906.53,846.53 1930,870 1930,927.63 1894.63,963 1877,963 1875.59,964.41 1875.59,985 C42.1@1884.08,985 ; U6.35@1877.13,1051.6 1878.07,1050.66 1878.07,1037.52 1881.93,1033.66 1881.93,1010.85 1896.7,996.08 1896.7,991.11 C42.1@1880.59,975
XTAL2: C41.2 U6.36 X2.3 | length 190.2
  Top Layer 1 w6: U6.36@1892.87,1051.6 1892.87,1014.05 1916.84,990.08 1924.33,990.08 1929.41,985 C41.2@1945,985 ; C41.2@1939.41,975 1920.58,956.17 1920.58,951.2 1937.69,934.09 1943.75,934.09 1958.31,919.53 X2.3@1958.31,913.47
pads on no net: *1.1 *2.1 *.1 U2.4 U2.5 U3.39 U3.42 U3.57 U3.58 U3.59 U3.60 U3.61 U3.63 U3.64 U6.24 U6.31 U8.4 U10.10 U10.11 U10.12 U10.17 U10.18 U10.19 U10.20 U11.10 U11.11 U11.12 U11.17 U11.18 U11.19 U11.20 U16.11 U16.12 U16.14 U16.15 U16.16 U16.22 U19.6 USB3.A8 USB3.B8

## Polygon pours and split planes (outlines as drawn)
GND on Bottom Layer 1 "GND_L04_P037" (solid, pour order 37): 1088.3,1633.3 1088.3,1659 1109,1659 1130,1680 1130,1815 1150,1835 1300,1835 1340,1795 1340,1500 1320,1480 1260,1480 1250,1470 1250,1420 1285,1385 1415,1385 1415,1380.7 1425,1370.7 1425,1340 1420,1340 1390,1310 1262.78,1310 1085.21,1409.88
+5V on Bottom Layer 1 "+5V_L04_P009" (solid, pour order 9): 860,1745 955,1840 1105,1840 1130,1815 1130,1675 1085,1630 1085,1435 945,1295 825,1295 780,1340 775,1645
1V05_SYS on Bottom Layer 1 "1V05_SYS_L04_P064" (solid, pour order 64): 1100.25,1409.75 1130,1380 1130,1285 1165,1250 1165,1220 1150,1205 1005,1205 995,1195 995,1185 1025,1155 1025,1125 1020,1125 1005,1110 985,1110 980,1105 980,1015 1025,970 1205,970 1245,930 1295,930 1315,950 1315,1015 1295,1035 1270,1035 1260,1045 1260,1210 1275,1225 1310,1225 1330,1205 1330,1080 1380,1030 1380,935 1330,885 985,885 910,960 910,1260 1054.83,1404.83 1054.83,1406.83 1058.17,1410.17
NetR33_1 on Bottom Layer 1 "NETR33_1_L04_P070" (solid, pour order 70): 2055,325 2055,510.82 2110.82,455 2110.82,437.96 2115,433.78 2115,310 2080,275 2070,275 2055,290
GND on Bottom Layer 1 "GND_L04_P069" (solid, pour order 69): 1030,155 1030,170 1050,190 1135,275 1225,275 1375,425 1375,615 1205,785 1255,835 1362.32,835 1387.32,860 1660,860 1905,615 1905,475 1720,290 1665,290 1650,305 1650,340 1670,360 1670,515 1632.5,552.5 1424.67,552.5 1398.03,525.86 1398.03,65.86 1428.89,35 1035,35
GND on Bottom Layer 1 "GND_L04_P068" (solid, pour order 68): 890,815 900,815 930,785 1180,785 1350,615 1350,435 1215,300 1005,300 985,320 985,330 1015,360 1015,510 890,635 890,685
GND on Bottom Layer 1 "GND_L04_P067" (solid, pour order 67): 370,220 435,220 555,340 625,340 690,405 690,800 735,845 870,845 890,825 890,570 865,545 775,545 750,520 750,60 780,30 350,30 325,55 325,175
GND on Bottom Layer 1 "GND_L04_P066" (solid, pour order 66): 292.5,342.5 300,350 300,745 580,1025 665,1110 870,1110 900,1080 900,995 885,980 880,985 770,985 675,890 675,415 615,355 530,355 410,235 350,235 299.47,285.53 285,285.53
VDD1V0 on Bottom Layer 1 "VDD1V0_L04_P055" (solid, pour order 55): 1820,1275 1835,1290 1990,1290 2030,1250 2030,1040 1991.44,1001.44 1891.97,1001.44 1758.08,1001.44 1728.85,1030.67 1730,1031.82 1730,1035 1740,1035 1750,1045 1750,1100 1825,1025 1862.14,1025 1875,1037.86 1875,1050 1895,1050 1905,1040 1970,1040 1985,1055 1985,1105 1950,1140 1950,1230 1930,1250 1825,1250
SYS+5V on Bottom Layer 1 "SYS+5V_L04_P029" (solid, pour order 29): 955,255 990,255 995,250 995,200 1010,185 1025,185 1035,175 1035,35 1025,25 985,25 955,55 955,180 940,195 940,240 940,195 940,240
GND on Bottom Layer 1 "GND_L04_P041" (solid, pour order 41): 65,525 90,550 180,550 180,544 225,499 225,295 255,265 255,200 270,185 270,60 300,30 100,30 65,65
SYS+5V on Bottom Layer 1 "SYS+5V_L04_P028" (solid, pour order 28): 245,255 280,255 285,250 285,200 300,185 315,185 325,175 325,35 315,25 275,25 245,55 245,180 230,195 230,240 230,195 230,240
3V3_SYS on Bottom Layer 1 "3V3_SYS_L04_P065" (solid, pour order 65): 1425,1310 1440,1295 1440,1265 1410,1235 1285,1235 1265,1215 1240,1215 1230,1205 1195,1205 1165,1235 1165,1280 1195,1310 1245,1310
VBUS2 on Bottom Layer 1 "VBUS2_L04_P032" (solid, pour order 32): 180,560 200,580 215,580 220,585 265,585 300,550 300,350 285,335 285,275 275,265 235,265 215,285 215,350 205,360 205,495 180,520 180,540
GND on Bottom Layer 1 "GND_L04_P043" (solid, pour order 43): 1622.5,1005 1624.2,1006.7 1661.7,1006.7 1690,1035 1730,1035 1768.83,996.17 2071.34,993.66 2095,970 2095,620 2030,555 2030,530 2015,515 1940,515 1930,525 1935,530 1935,640 1645,930 1585,990 1585,1005
VDD1V0 on Bottom Layer 1 "VDD1V0_L04_P019" (solid, pour order 19): 1595,1105 1745,1105 1750,1100 1750,1045 1740,1035 1690,1035 1660,1005 1585,1005 1575,1015 1575,1085
GND on Bottom Layer 1 "GND_L04_P053" (solid, pour order 53): 1700,160 1720,255 1920,455 1920,515 1935,530 2030,530 2050,510 2050,40 2030,20 1765,20 1725,60 1705,85
SYS+5V on Bottom Layer 1 "SYS+5V_L04_P031" (solid, pour order 31): 1605,270 1640,270 1645,265 1645,215 1660,200 1675,200 1685,190 1685,50 1675,40 1635,40 1605,70 1605,195 1590,210 1590,255 1590,210 1590,255
GND on Bottom Layer 1 "GND_L04_P001" (solid, pour order 1): 405,1420 540,1420 560,1440 560,1455 545,1470 495,1470 415,1550 40,1550 5,1515 5,1010 125,890 540,890 565,915 565,1055 555,1065 515,1025 410,1025 320,1115 320,1190 215,1295 215,1400 230,1415 230,1420 355,1420
GND on Bottom Layer 1 "GND_L04_P042" (solid, pour order 42): 1398.03,525.86 1427.17,555 1513.03,555 1513.03,544.86 1558.03,499.86 1558.03,295.86 1588.03,265.86 1588.03,200.86 1603.03,185.86 1603.03,60.86 1633.03,30.86 1433.03,30.86 1398.03,65.86
GND on Bottom Layer 1 "GND_L04_P040" (solid, pour order 40): 750,520 775,545 865,545 865,539 910,494 910,290 940,260 940,195 955,180 955,55 985,25 785,25 750,60
VBUS3 on Bottom Layer 1 "VBUS3_L04_P036" (solid, pour order 36): 1525,575 1535,585 1600,585 1670,515 1670,360 1650,340 1650,280 1640,270 1595,270 1560,305 1560,360 1575,375 1575,500 1565,510 1545,510 1525,530
VBUS4 on Bottom Layer 1 "VBUS4_L04_P035" (solid, pour order 35): 880,575 950,575 990,535 1015,510 1015,360 985,330 985,270 980,265 935,265 910,290 910,480 905,485 905,500 865,540 865,565
GND_ISO on Bottom Layer 1 "GND_ISO_L04_P054" (solid, pour order 54): 2680,1245 2675,1265 2675,1520 2790,1635 3190,1635 3345,1480 3345,750 3230,635 3040,635 2895,780 2895,915 2735,1075
NetR33_1 on Bottom Layer 1 "NETR33_1_L04_P048" (solid, pour order 48): 2050,555 2085,590 2520,590 2580,650 2580,710 2595,725 2655,725 2710,670 2710,515 2650,455 2085,455 2050,490 2050,510
SW on Bottom Layer 1 "SW_L04_P002" (solid, pour order 2): 526.01,1420 590,1420 610,1440 610,1495 620,1505 725,1505 735,1495 735,1355 730,1350 615,1350 605,1360 605,1400 600,1400 595,1405 526.01,1405
VIN on Bottom Layer 1 "VIN_L04_P000" (solid, pour order 0): 230,1420 505,1420 520,1405 545,1405 560,1390 560,1070 515,1025 410,1025 320,1115 320,1190 215,1295 215,1400
SYS+5V on Top Layer 1 "SYS+5V_L01_P058" (solid, pour order 58): 1490,1840 1490,1540 1450,1500 1450,1455 1445,1450 1430,1450 1425,1455 1425,1490 1345,1570 1345,1745 1395,1745 1420,1770
GND on Top Layer 1 "GND_L01_P072" (solid, pour order 72): 1965,1830 2175,1830 2200,1855 2200,1915 2220,1935 2260,1935 2275,1920 2275,1780 2225,1730 1970,1730 1945,1755 1945,1815
SYS+5V on Top Layer 1 "SYS+5V_L01_P071" (solid, pour order 71): 1940,1910 1965,1935 2175,1935 2200,1910 2200,1855 2175,1830 1965,1830 1940,1855
+5V on Top Layer 1 "+5V_L01_P022" (solid, pour order 22): 1009.47,1810 1012.87,1813.4 1101.6,1813.4 1115,1800 1115,1750 1100,1735 1050,1735 1035,1750 1035,1780 1030,1785 1015,1785 1009.47,1790.53
SYS+5V on Top Layer 1 "SYS+5V_L01_P061" (solid, pour order 61): 995,1650 995,1675 1015,1695 1125,1695 1155,1725 1155,1775 1160,1780 1210,1730 1225,1730 1240,1715 1240,1660 1210,1630 1055,1630 1045,1620 1045,1580 1040,1575 1020,1575 995,1600 995,1645
3V3_SYS on Top Layer 1 "3V3_SYS_L01_P060" (solid, pour order 60): 1305,1505 1320,1520 1350,1520 1365,1505 1365,1425 1385,1405 1425,1405 1445,1385 1445,1305 1425,1285 1355,1285 1345,1295 1345,1360 1345,1390 1330,1405 1315,1405 1305,1415
NetU4_1 on Top Layer 1 "NETU4_1_L01_P059" (solid, pour order 59): 1375,1505 1410,1505 1427.5,1487.5 1427.5,1452.5 1435,1445 1435,1440 1440,1440 1450,1430 1450,1410 1445,1405 1385,1405 1370,1420 1370,1500
GND on Top Layer 1 "GND_L01_P044" (solid, pour order 44): 0,470 145,470 145,460 215,390 520,390 670,540 830,540 980,390 1225,390 1290,455 1485,455 1525,415 1840,415 1905,480 1985,480 1995,470 1995,420 2165,250 2175,250 2175,0 115,0 85,30 50,30 30,50 30,70 5,95 5,135 -5,145
GND on Top Layer 1 "GND_L01_P045" (solid, pour order 45): 10,1860 45,1895 145,1895 195,1845 60,1710 60,1470 275,1255 320,1255 360,1215 360,1115 205,960 35,960 -5,1000 -5,1835
1V05_SYS on Top Layer 1 "1V05_SYS_L01_P063" (solid, pour order 63): 1070,1465 1070,1520 1080,1530 1110,1530 1135,1505 1135,1375 1125,1365 1075,1365 1050,1390 1050,1425 1065,1440 1065,1450
NetU5_1 on Top Layer 1 "NETU5_1_L01_P062" (solid, pour order 62): 1030,1565 1025,1560 1025,1535 1005,1515 1005,1445 1015,1435 1045,1435 1055,1445 1055,1515 1045,1525 1045,1560 1040,1565
SYS+5V on Top Layer 1 "SYS+5V_L01_P057" (solid, pour order 57): 960,1840 965,1845 1100,1845 1155,1900 1155,1930 1175,1950 1390,1950 1490,1850 1490,1840 1380,1730 1205,1730 1125,1810 970,1810 960,1820
SYS+5V on Top Layer 1 "SYS+5V_L01_P016" (solid, pour order 16): 1635,1175 1700,1175 1720,1155 1755,1155 1770,1140 1770,1135 1805,1135 1810,1130 1810,1120 1808.57,1118.57 1763.57,1118.57 1745,1100 1650,1100 1620,1130 1620,1165
SW2 on Top Layer 1 "SW2_L01_P017" (solid, pour order 17): 1688.33,1100 1745,1100 1763.57,1118.57 1806.35,1118.57 1810,1114.91 1810,1105 1805,1100 1770,1100 1765,1095 1765,1020 1745,1000 1700,1000 1680,1020 1680,1090
GND_ISO on Top Layer 1 "GND_ISO_L01_P047" (solid, pour order 47): 2895,520 2910,535 3000,535 3050,485 3245,485 3320,560 3450,560 3520,490 3520,80 3445,5 2975,5 2895,85 2895,115
ISO+5V on Top Layer 1 "ISO+5V_L01_P015" (solid, pour order 15): 2620,1945 2980,1945 3050,1875 3050,1835 3045,1830 2870,1830 2805,1765 2605,1765 2570,1800 2570,1895
VDD1V0 on Top Layer 1 "VDD1V0_L01_P018" (solid, pour order 18): 1680,1090 1665,1105 1595,1105 1580,1090 1580,1010 1605,985 1660,985 1680,1005 1680,1030
SYS+5V on Layer2 "SYS+5V_L03_P056" (solid, pour order 56): 1250,1915 1285,1950 2170,1950 2205,1915 2205,915 2130,840 2015,725 2015,45 1990,20 105,20 40,85 40,680 230,870 1210,870 1315,975 1315,1305 1200,1420 1205,1870
GND on Layer2 "GND_L03_P021" (solid, pour order 21): 80,1705 195,1795 440,1795 530,1705 530,1505 425,1400 120,1400 80,1440 80,1535
SYS+5V on Layer2 "SYS+5V_L03_P007" (solid, pour order 7): 1310,1835 1315,1840 1315,1935 1330,1950 1445,1950 1480,1915 1480,1750 1430,1700 1305,1700 1285,1720 1285,1800
GND on Layer1 "GND_L02_P024" (solid, pour order 24): -5,1825 0,1830 0,1855 10,1865 10,1880 25,1895 25,1900 80,1955 95,1955 110,1970 2235,1970 2275,1930 2275,1155 2652.5,777.5 2659.93,-9.98 115,0 95,20 80,20 60,40 55,40 25,70 25,75 15,85 15,100 10,105 10,115 0,125 0,1800 -5,1805
GND_ISO on Layer1 "GND_ISO_L02_P025" (solid, pour order 25): 2430,1950 2445,1965 2455,1965 3440,1965 3465,1940 3480,1940 3510,1910 3510,1905 3535,1880 3535,1850 3545,1840 3545,155 3535,145 3535,100 3510,75 3510,55 3495,40 3480,40 3450,10 3425,10 3415,0 2890,0 2890,885 2805,970 2660,970 2430,1200 2430,1265

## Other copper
Layer1:
  pour cut-out: 2080,20 2085,25 2085,840 2590,840 2659.9,770.1 2659.9,-6.42 2086.42,-6.42 2080,0

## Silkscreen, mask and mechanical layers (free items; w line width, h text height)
Top Overlay:
  lines w10: 3145,725 3265,725 ; 3145,815 3265,815 ; 3145,910 3265,910 ; 3145,1015 3265,1015 ; 3145,1115 3260,1115 ; 3145,1220 3265,1220 ; 3145,1320 3265,1320 ; 3145,1415 3265,1415 ; 3145,1510 3265,1510 ; 3145,1610 3265,1610 ; 3205,640 3205,1715 ; 3145,640 3265,640 3265,1715 3145,1715 3145,640 ; 3270,1810 3435,1810 3435,1895 3270,1895 3270,1810
  text "TXD0" at 3316,1829 h15 r90
  text "RTS0" at 3406,1829 h15 r90
  text "MOSI" at 3241,1639 h15 r90
  text "CTS0" at 3181,1634 h15 r90
  text "MISO" at 3181,1534 h15 r90
  text "SCK" at 3241,1534 h15 r90
  text "SCS0" at 3181,1439 h15 r90
  text "SDA" at 3241,1439 h15 r90
  text "SCL" at 3181,1344 h15 r90
  text "DTR0" at 3241,1344 h15 r90
  text "TRST" at 3181,1244 h15 r90
  text "ACT" at 3241,1244 h15 r90
  text "SCS1" at 3181,1139 h15 r90
  text "RXD1" at 3241,1139 h15 r90
  text "TXD1" at 3181,1039 h15 r90
  text "RXD0" at 3241,1039 h15 r90
  text "TCK" at 3181,934 h15 r90
  text "TDO" at 3241,934 h15 r90
  text "TDI" at 3181,839 h15 r90
  text "TMS/" at 3241,839 h15 r90
  text "GND" at 3181,749 h15 r90
  text "GND" at 3241,749 h15 r90
  text "GND" at 3181,664 h15 r90
  text "GND" at 3241,664 h15 r90
Mechanical 1:
  lines w10: 0,157.48 ccw(c157.48,157.48) 157.48,0 3385.83,0 ccw(c3385.83,157.48) 3543.31,157.48 3543.31,1811.02 ccw(c3385.83,1811.02) 3385.83,1968.5 157.48,1968.5 ccw(c157.48,1811.02) 0,1811.02 0,157.48 ; 2325,1160 2325,1350 2355,1380 2355,1852.91 2362.09,1860 2387.09,1860 2395,1852.09 2395,1330 2365,1300 2365,1240 2365,1190 2620,935 2720,935 2820,835 2820,140 2810,130 2780,130 2770,140 2770,820 2695,895 2590,895 2325,1160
